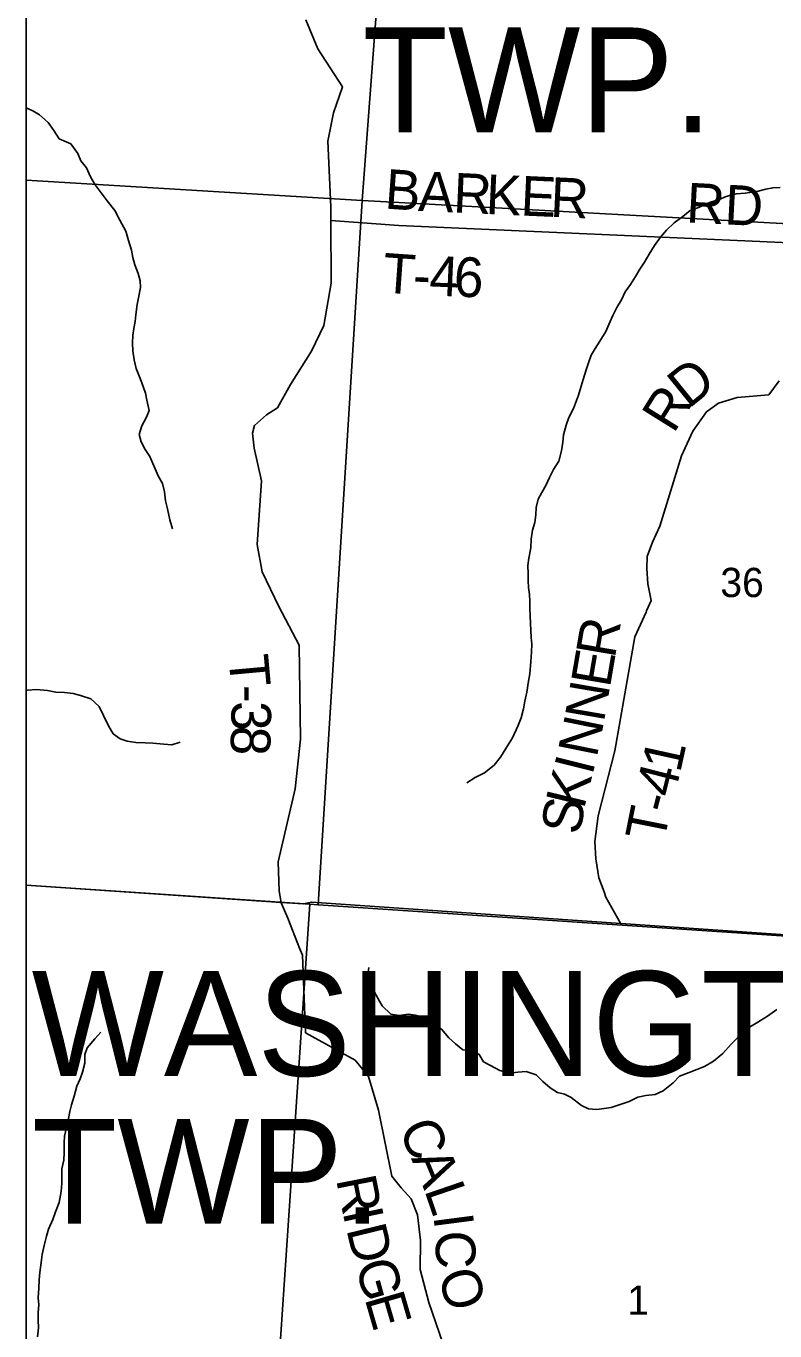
# Model space of a CAD drawing. Extents: x 0 to 34, y 0 to 22.
# Drawn here: x 2.1 to 3.172, y 18.443 to 20.311 of the extents above; entities that cross this region are included whole.
import ezdxf

# ---------------------------------------------------------------- set-up
doc = ezdxf.new("R2010")
doc.units = 0
for name, color, linetype in [('GM_X_Corporation', 7, 'Continuous'), ('GM_X_Minor_River', 7, 'Continuous'), ('GM_X_Section_Text', 7, 'Continuous'), ('GM_X_Township_Road', 7, 'Continuous'), ('GM_X_Township_Road_Text', 7, 'Continuous'), ('GM_X_Township_Text', 7, 'Continuous'), ('SH_Data', 7, 'Continuous')]:
    doc.layers.add(name, color=color, linetype=linetype)

msp = doc.modelspace()

# ---------------------------------------------------------------- linework, layer by layer
at = {"layer": 'GM_X_Corporation'}
for points in [[(2.6442, 20.9), (2.1, 20.9), (2.1, 20.0905), (2.5811, 20.0615)], [(3.646, 20.9), (2.6442, 20.9), (2.5811, 20.0615), (3.5832, 20.0065)], [(2.1, 20.0905), (2.1, 19.0812), (2.5061, 19.0541), (2.5182, 19.0533), (2.5811, 20.0615)], [(2.5811, 20.0615), (3.5832, 20.0065), (3.5166, 18.9866), (2.5182, 19.0533)], [(2.1, 19.0816), (2.1, 14.1), (3.1902, 14.1), (3.1919, 14.1255), (3.2339, 14.7735), (3.2844, 15.554), (3.3059, 15.8844), (3.3516, 16.5898), (3.3951, 17.2616), (3.507, 18.9883), (2.9513, 19.0267), (2.509, 19.0572), (2.4972, 19.0545), (2.4649, 19.0567)], [(2.1, 19.0812), (2.1, 18.0323), (2.436, 18.0137), (2.5061, 19.0541)], [(2.5061, 19.0541), (2.5182, 19.0533), (3.5166, 18.9866), (3.4457, 17.9455), (2.436, 18.0137)]]:
    msp.add_lwpolyline(points, close=True, dxfattribs=at)
at = {"layer": 'GM_X_Minor_River'}
for p, q in [((2.1, 20.1944), (2.1095, 20.19)), ((2.1095, 20.19), (2.119, 20.1844)), ((2.119, 20.1844), (2.1316, 20.1734)), ((2.1316, 20.1734), (2.1399, 20.1617)), ((2.1399, 20.1617), (2.1475, 20.15)), ((2.1475, 20.15), (2.1642, 20.1429)), ((2.1642, 20.1429), (2.1741, 20.1289)), ((2.1741, 20.1289), (2.1783, 20.1183)), ((2.1783, 20.1183), (2.1867, 20.1085)), ((2.1867, 20.1085), (2.1924, 20.0956)), ((2.1924, 20.0956), (2.1989, 20.0839)), ((2.1989, 20.0839), (2.216, 20.0612)), ((2.216, 20.0612), (2.227, 20.0473)), ((2.227, 20.0473), (2.2342, 20.0333)), ((2.2342, 20.0333), (2.243, 20.0178)), ((2.243, 20.0178), (2.2464, 20.0041)), ((2.2464, 20.0041), (2.251, 19.9905)), ((2.251, 19.9905), (2.253, 19.9799)), ((2.253, 19.9799), (2.2557, 19.9693)), ((2.2557, 19.9693), (2.2602, 19.9572)), ((2.2602, 19.9572), (2.2633, 19.9466)), ((2.2637, 19.9368), (2.2611, 19.9223)), ((2.2633, 19.9466), (2.2637, 19.9368)), ((2.2611, 19.9223), (2.2589, 19.9129)), ((2.257, 19.8977), (2.2563, 19.8882)), ((2.2589, 19.9129), (2.257, 19.8977)), ((2.2541, 19.8784), (2.253, 19.8689)), ((2.2563, 19.8882), (2.2541, 19.8784)), ((2.253, 19.8689), (2.2523, 19.8575)), ((2.2523, 19.8575), (2.2527, 19.8465)), ((2.2527, 19.8465), (2.2546, 19.8336)), ((2.2546, 19.8336), (2.2577, 19.8211)), ((2.2577, 19.8211), (2.2615, 19.8113)), ((2.2615, 19.8113), (2.2657, 19.8007)), ((2.2657, 19.8007), (2.2707, 19.7859)), ((2.2707, 19.7859), (2.273, 19.7757)), ((2.273, 19.7757), (2.2761, 19.761)), ((2.2723, 19.7515), (2.2655, 19.7389)), ((2.2761, 19.761), (2.2723, 19.7515)), ((2.2655, 19.7389), (2.2618, 19.7264)), ((2.2618, 19.7264), (2.2649, 19.7162)), ((2.2649, 19.7162), (2.2706, 19.7052)), ((2.2706, 19.7052), (2.2771, 19.695)), ((2.2771, 19.695), (2.2889, 19.6674)), ((2.2889, 19.6674), (2.2952, 19.6566)), ((2.2952, 19.6566), (2.2981, 19.6443)), ((2.2981, 19.6443), (2.2996, 19.6318)), ((2.2996, 19.6318), (2.3023, 19.6201)), ((2.3023, 19.6201), (2.3058, 19.6042)), ((2.3058, 19.6042), (2.3096, 19.5913)), ((2.1, 19.3601), (2.1019, 19.3603)), ((2.1019, 19.3603), (2.1151, 19.3615)), ((2.1151, 19.3615), (2.1306, 19.3601)), ((2.1306, 19.3601), (2.1424, 19.3575)), ((2.1424, 19.3575), (2.1552, 19.3572)), ((2.1552, 19.3572), (2.1674, 19.3557)), ((2.1674, 19.3557), (2.178, 19.3531)), ((2.178, 19.3531), (2.1927, 19.3479)), ((2.1927, 19.3479), (2.2045, 19.3373)), ((2.2045, 19.3373), (2.211, 19.3241)), ((2.211, 19.3241), (2.2179, 19.3093)), ((2.2179, 19.3093), (2.2247, 19.298)), ((2.2247, 19.298), (2.2346, 19.2908)), ((2.2346, 19.2908), (2.2448, 19.2875)), ((2.2448, 19.2875), (2.2573, 19.2856)), ((2.2573, 19.2856), (2.2706, 19.2849)), ((2.2706, 19.2849), (2.2815, 19.2846)), ((2.2815, 19.2846), (2.2974, 19.2831)), ((2.2974, 19.2831), (2.3084, 19.2824)), ((2.3084, 19.2824), (2.3205, 19.2859)), ((2.1982, 18.8612), (2.2069, 18.8711)), ((2.1843, 18.8388), (2.1873, 18.8487)), ((2.1873, 18.8487), (2.1982, 18.8612)), ((2.184, 18.8263), (2.1843, 18.8388)), ((2.1773, 18.8039), (2.1806, 18.8138)), ((2.1806, 18.8138), (2.184, 18.8263)), ((2.1686, 18.7793), (2.1724, 18.7937)), ((2.1724, 18.7937), (2.1773, 18.8039)), ((2.1649, 18.7671), (2.1686, 18.7793)), ((2.16, 18.7451), (2.1627, 18.7572)), ((2.1627, 18.7572), (2.1649, 18.7671)), ((2.1578, 18.7345), (2.16, 18.7451)), ((2.1545, 18.7125), (2.1548, 18.722)), ((2.1548, 18.722), (2.1578, 18.7345)), ((2.1545, 18.6985), (2.1545, 18.7125)), ((2.1512, 18.6753), (2.1538, 18.6878)), ((2.1538, 18.6878), (2.1545, 18.6985)), ((2.1513, 18.6541), (2.1512, 18.6753)), ((2.1502, 18.6427), (2.1513, 18.6541)), ((2.142, 18.6139), (2.1472, 18.6272)), ((2.1472, 18.6272), (2.1502, 18.6427)), ((2.1382, 18.6029), (2.142, 18.6139)), ((2.1292, 18.579), (2.1322, 18.5888)), ((2.1322, 18.5888), (2.1382, 18.6029)), ((2.1259, 18.5653), (2.1292, 18.579)), ((2.1214, 18.541), (2.1229, 18.5528)), ((2.1229, 18.5528), (2.1259, 18.5653)), ((2.1196, 18.5266), (2.1214, 18.541)), ((2.1181, 18.5046), (2.1188, 18.5164)), ((2.1188, 18.5164), (2.1196, 18.5266)), ((2.1174, 18.4906), (2.1181, 18.5046)), ((2.1171, 18.4694), (2.1182, 18.4804)), ((2.1182, 18.4804), (2.1174, 18.4906)), ((2.1171, 18.4588), (2.1171, 18.4694)), ((2.1176, 18.4474), (2.1171, 18.4588)), ((2.1161, 18.4345), (2.1176, 18.4474))]:
    msp.add_line(p, q, dxfattribs=at)
for points in [[(3.1795, 20.08), (3.1689, 20.0799), (3.1587, 20.078), (3.1462, 20.0745), (3.1292, 20.0722), (3.1163, 20.0713), (3.1023, 20.0675), (3.0921, 20.0629), (3.0781, 20.0587), (3.0638, 20.0522), (3.0505, 20.0472), (3.04, 20.0388), (3.0275, 20.0296), (3.0166, 20.0193), (3.0083, 20.0091), (2.9996, 19.9973), (2.9917, 19.9847), (2.9853, 19.9733), (2.9786, 19.9635), (2.9725, 19.9528), (2.9654, 19.9414), (2.9575, 19.9308), (2.9522, 19.9194), (2.9458, 19.9084), (2.9398, 19.897), (2.9342, 19.8841), (2.93, 19.8742), (2.9214, 19.8601), (2.9146, 19.8499), (2.909, 19.84), (2.9049, 19.829), (2.9019, 19.8191), (2.8974, 19.8054), (2.8944, 19.7956), (2.8906, 19.783), (2.8835, 19.7637), (2.8771, 19.7511), (2.873, 19.7401), (2.8693, 19.7261), (2.8682, 19.7155), (2.8663, 19.7033), (2.8626, 19.6885), (2.8551, 19.6764), (2.8494, 19.665), (2.8445, 19.6544), (2.8385, 19.6437), (2.8329, 19.6342), (2.8303, 19.6221), (2.8299, 19.6115), (2.8281, 19.6005), (2.8251, 19.5898), (2.8229, 19.5766), (2.8225, 19.5641), (2.8199, 19.5496), (2.8184, 19.539), (2.8185, 19.5273), (2.8189, 19.517), (2.8193, 19.5076), (2.8205, 19.4973), (2.8213, 19.4879), (2.8213, 19.4776), (2.8217, 19.4667), (2.8221, 19.4564), (2.8226, 19.4458), (2.823, 19.436)], [(2.823, 19.436), (2.8238, 19.4265), (2.8234, 19.4151), (2.8223, 19.4018), (2.8213, 19.384), (2.8194, 19.3734), (2.8168, 19.3575), (2.8138, 19.345), (2.812, 19.334), (2.8086, 19.3211), (2.8041, 19.3089), (2.7962, 19.2922), (2.7868, 19.277), (2.7789, 19.2648), (2.7699, 19.2534), (2.7563, 19.2424), (2.7427, 19.2355), (2.731, 19.2279)], [(2.7646, 18.8232), (2.7547, 18.8285), (2.7486, 18.8387), (2.7369, 18.844), (2.7251, 18.8458), (2.7149, 18.8541), (2.705, 18.8628), (2.6948, 18.8752), (2.6815, 18.8877), (2.669, 18.8925), (2.6572, 18.8951), (2.6474, 18.8966), (2.6341, 18.8947), (2.622, 18.8969), (2.6099, 18.9086), (2.6038, 18.9184), (2.5984, 18.929), (2.5931, 18.9422), (2.5893, 18.954), (2.5904, 18.9634)], [(3.1746, 18.9035), (3.1613, 18.894), (3.1477, 18.8852), (3.1334, 18.8764), (3.1202, 18.8646), (3.1093, 18.8536), (3.0976, 18.8403), (3.084, 18.8296), (3.0711, 18.8216), (3.0492, 18.8131), (3.0352, 18.8078), (3.0262, 18.7983), (3.0122, 18.7868), (3.0005, 18.7818), (2.9873, 18.7803), (2.9759, 18.7779), (2.9631, 18.7718), (2.9491, 18.7668), (2.9377, 18.763), (2.9275, 18.7614), (2.9166, 18.7602), (2.9052, 18.761), (2.895, 18.7658), (2.8802, 18.7775), (2.8707, 18.782), (2.8608, 18.7843), (2.8502, 18.791), (2.8396, 18.8005), (2.8301, 18.8099), (2.8157, 18.8147), (2.804, 18.8136), (2.7919, 18.812), (2.7782, 18.8161), (2.7646, 18.8232)]]:
    msp.add_lwpolyline(points, dxfattribs=at)
at = {"layer": 'GM_X_Township_Road'}
for points in [[(2.4916, 18.9912), (2.4745, 19.0341), (2.4651, 19.0562), (2.4622, 19.0734), (2.4608, 19.1148), (2.485, 19.2195), (2.4929, 19.2905), (2.4909, 19.4248), (2.4617, 19.4802), (2.4378, 19.5299), (2.4309, 19.5689), (2.437, 19.6604), (2.4263, 19.7071), (2.424, 19.7283), (2.4271, 19.7393), (2.4441, 19.7545), (2.4597, 19.7648), (2.4783, 19.7982), (2.5086, 19.8461), (2.5264, 19.8825), (2.5367, 19.9433), (2.5363, 20.0328), (2.5362, 20.0526), (2.532, 20.1463), (2.54, 20.1869), (2.5529, 20.2245), (2.5175, 20.2787), (2.5005, 20.3201)], [(2.5363, 20.0328), (2.6335, 20.026), (3.1933, 20.0011)], [(2.9273, 19.0718), (2.9198, 19.0917), (2.9158, 19.119), (2.9141, 19.144), (2.9187, 19.1805), (2.9426, 19.2738), (2.9714, 19.4369), (2.9874, 19.4722), (2.9883, 19.4742), (2.995, 19.4891), (2.9902, 19.5128), (2.9885, 19.5348), (2.9889, 19.5519), (2.9966, 19.5722), (3.007, 19.5955), (3.023, 19.6464), (3.0382, 19.6962), (3.0542, 19.7315), (3.0738, 19.7588), (3.0912, 19.7713), (3.1179, 19.7795), (3.1632, 19.7834), (3.1781, 19.8032)], [(2.9515, 19.0261), (2.9301, 19.0643), (2.9273, 19.0718)], [(2.7147, 18.3683), (2.7016, 18.4104), (2.6765, 18.484), (2.664, 18.531), (2.6644, 18.5728), (2.6605, 18.6092), (2.651, 18.6323), (2.637, 18.6482), (2.6237, 18.6649), (2.6047, 18.7594), (2.5903, 18.8076), (2.5713, 18.8307), (2.4999, 18.87), (2.4984, 18.9072), (2.4956, 18.9812), (2.4916, 18.9912)]]:
    msp.add_lwpolyline(points, dxfattribs=at)
at = {"layer": 'GM_X_Township_Text'}
msp.add_lwpolyline([(2.1, 19.0816), (2.4649, 19.0567), (2.4972, 19.0545), (2.509, 19.0572), (2.9513, 19.0267), (3.507, 18.9883), (3.566, 19.7906), (3.5665, 19.797), (3.6464, 20.8827), (3.6477, 20.9)], dxfattribs=at)
at = {"layer": 'SH_Data'}
msp.add_line((2.1, 20.9), (2.1, 14.1), dxfattribs=at)

# ---------------------------------------------------------------- texts
at = {"layer": 'GM_X_Section_Text'}
for s, height, p in [('36', 0.04186, (3.0938, 19.4938)), ('1', 0.0419, (2.9605, 18.4663))]:
    msp.add_text(s, height=height, rotation=0, dxfattribs=at).set_placement(p)
at = {"layer": 'GM_X_Township_Road_Text'}
for s, height, rotation, p in [('B', 0.0568, 355.8515, (2.6123, 20.0502)), ('A', 0.0568, 357.3954, (2.6606, 20.0468)), ('R', 0.0568, 357.4516, (2.7106, 20.0445)), ('K', 0.0568, 357.4457, (2.7572, 20.0424)), ('E', 0.0568, 357.4499, (2.8071, 20.0402)), ('R', 0.0568, 357.4467, (2.8496, 20.0383)), ('RD', 0.05682, 357.0406, (3.0441, 20.0304)), ('T', 0.0568, 355.9638, (2.609, 19.93)), ('4', 0.0568, 357.5766, (2.6765, 19.9258)), ('6', 0.0568, 357.6525, (2.7115, 19.9243)), ('-', 0.0568, 357.4043, (2.653, 19.9269)), ('D', 0.0568, 39.0313, (3.0483, 19.7625)), ('R', 0.0568, 58.0248, (3.0269, 19.7266)), ('R', 0.0568, 80.2816, (2.9427, 19.4048)), ('T', 0.0568, 275.2014, (2.3896, 19.409)), ('E', 0.0568, 80.2856, (2.9356, 19.3629)), ('-', 0.0568, 270.7338, (2.3934, 19.3678)), ('N', 0.0568, 80.2095, (2.927, 19.3135)), ('3', 0.0568, 270.4684, (2.3937, 19.3446)), ('N', 0.0568, 78.5419, (2.9168, 19.2628)), ('8', 0.0568, 267.3764, (2.394, 19.3104)), ('1', 0.0568, 77.6475, (3.0362, 19.241)), ('I', 0.0568, 75.9013, (2.9105, 19.2373)), ('K', 0.0568, 76.1917, (2.8985, 19.1889)), ('4', 0.0568, 75.6547, (3.027, 19.205)), ('S', 0.0568, 81.5594, (2.8932, 19.1523)), ('-', 0.0568, 75.5946, (3.0212, 19.1823)), ('T', 0.0568, 78.6985, (3.0131, 19.1414)), ('C', 0.0568, 292.7712, (2.6327, 18.7333)), ('A', 0.0568, 292.6294, (2.6508, 18.6903)), ('R', 0.0568, 281.2181, (2.5436, 18.6603)), ('L', 0.0568, 288.9256, (2.6697, 18.6451)), ('I', 0.0568, 282.0259, (2.5529, 18.6137)), ('I', 0.0568, 277.4368, (2.6828, 18.6078)), ('D', 0.0568, 283.7249, (2.5581, 18.589)), ('C', 0.0568, 271.4755, (2.6857, 18.5862)), ('G', 0.0568, 285.7732, (2.5706, 18.5383)), ('O', 0.0568, 285.7139, (2.6892, 18.5244)), ('E', 0.0568, 286.1901, (2.5843, 18.4898))]:
    msp.add_text(s, height=height, rotation=rotation, dxfattribs=at).set_placement(p)
at = {"layer": 'GM_X_Township_Text'}
for s, p in [('TWP.', (2.5814, 20.1593)), ('WASHINGTON', (2.108, 18.8083)), ('TWP.', (2.108, 18.5967))]:
    msp.add_text(s, height=0.15, rotation=0, dxfattribs=at).set_placement(p)

doc.saveas('drawing.dxf')
